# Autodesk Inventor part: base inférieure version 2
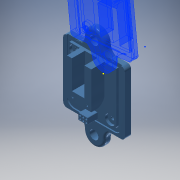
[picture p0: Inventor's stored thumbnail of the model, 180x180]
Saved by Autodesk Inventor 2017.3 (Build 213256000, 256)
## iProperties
Part Number: base inférieure version 2
Material: Plastique PMMA
Document SubType Name: Modeling
Designer: ficho
Density: 1.188 g/cm^3
Appearance: Pervenche
Mass: 23.0613 g
Surface Area: 101.506 cm^2
Volume: 19.4119 cm^3
Author: ficho
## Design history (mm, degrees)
node "Plan de construction1"
sketch "Esquisse1"
  geometry: L1 (4.5, -5.45)-(-4.5, -5.45) reference; L2 (4.5, 5.45)-(4.5, -5.45) reference; L3 (-4.5, 5.45)-(4.5, 5.45) reference; L4 (-4.5, -5.45)-(-4.5, 5.45) reference; L5 (-1.95, -7.7)-(4.55, -7.7) reference; L6 (-2.55, -9.12)-(-2.55, -8.3) reference; L7 (-2.096, -9.759)-(-2.308, -9.601) reference; L8 (-1.935, -10.8)-(-1.935, -10.08) reference; L9 (3.935, -11.4)-(-1.335, -11.4) reference; L10 (4.535, -10.08)-(4.535, -10.8) reference; L11 (4.908, -9.601)-(4.696, -9.759) reference; L12 (5.15, -8.3)-(5.15, -9.12) reference; L13 (-1.95, -8)-(4.55, -8) reference; L14 (4.85, -8.3)-(4.85, -9.12) reference; L15 (4.729, -9.361)-(4.517, -9.518) reference; L16 (4.235, -10.08)-(4.235, -10.8) reference; L17 (3.935, -11.1)-(-1.335, -11.1) reference; L18 (-1.635, -10.8)-(-1.635, -10.08) reference; L19 (-1.917, -9.518)-(-2.129, -9.361) reference; L20 (-2.25, -9.12)-(-2.25, -8.3) reference; L21 (-17.7, 15.45)-(20.2, 15.45); L22 (20.2, 15.45)-(20.2, -5.45); L23 (-17.7, -5.45)-(-17.7, 15.45); L24 (-5, -5.45)-(-17.7, -5.45); L25 (5, -5.45)-(20.2, -5.45); L26 (-5, -5.45)-(-5, 5.95); L27 (5, 5.95)-(5, -5.45); L28 (-5, 5.95)-(4.235, 5.95); L29 (4.5, 5.95)-(5, 5.95); L30 (-1.635, -5.95)-(-1.935, -5.95); L31 (-2.25, -5.95)-(-2.55, -5.95); L32 (5, -5.95)-(4.85, -5.95); L33 (4.535, -5.95)-(4.5, -5.95); L34 (4.5, 5.95)-(4.235, 5.95); C1 r 3.15 at (0, 0.95) reference; A1 r 0.6 centre (4.55, -8.3) between (5.15, -8.3) and (4.55, -7.7) reference; A2 r 0.6 centre (-1.95, -8.3) between (-1.95, -7.7) and (-2.55, -8.3) reference; A3 r 0.6 centre (-1.95, -9.12) between (-2.55, -9.12) and (-2.308, -9.601) reference; A4 r 0.4 centre (-2.335, -10.08) between (-1.935, -10.08) and (-2.096, -9.759) reference; A5 r 0.6 centre (-1.335, -10.8) between (-1.935, -10.8) and (-1.335, -11.4) reference; A6 r 0.6 centre (3.935, -10.8) between (3.935, -11.4) and (4.535, -10.8) reference; A7 r 0.4 centre (4.935, -10.08) between (4.696, -9.759) and (4.535, -10.08) reference; A8 r 0.6 centre (4.55, -9.12) between (4.908, -9.601) and (5.15, -9.12) reference; A9 r 0.3 centre (4.55, -8.3) between (4.85, -8.3) and (4.55, -8) reference; A10 r 0.3 centre (4.55, -9.12) between (4.729, -9.361) and (4.85, -9.12) reference; A11 r 0.7 centre (4.935, -10.08) between (4.517, -9.518) and (4.235, -10.08) reference; A12 r 0.3 centre (3.935, -10.8) between (3.935, -11.1) and (4.235, -10.8) reference; A13 r 0.3 centre (-1.335, -10.8) between (-1.635, -10.8) and (-1.335, -11.1) reference; A14 r 0.7 centre (-2.335, -10.08) between (-1.635, -10.08) and (-1.917, -9.518) reference; A15 r 0.3 centre (-1.95, -9.12) between (-2.25, -9.12) and (-2.129, -9.361) reference; A16 r 0.3 centre (-1.95, -8.3) between (-1.95, -8) and (-2.25, -8.3) reference; 3 further points
  constraints: 28 end point, 10 point on line, 2 perpendicular, 1 collinear, 1 horizontal, 1 parallel, 2 other
  dimensions: "d0" = 10 distance from line of point (-7.7, -6.45) L23; "d1" = 10 distance from line of L22 point (10.2, -6.45) (= d0); "d2" = 10 distance between parallel lines of L21 L3 (= d0); "d23" = 0.5 distance between parallel lines of L2 L27
extrude "Extrusion1" new body sketch "Esquisse1" stored distance "d4" = 1; taper "d5" = 0 deg
node "Plan de construction2"
sketch "Esquisse2"
  geometry: L1 (0, -20.9)-(15.2, -20.9) reference; L2 (25.34, -20.9)-(29.34, -20.9); L3 (29.34, -20.9)-(29.34, -4.794); L4 (29.34, -4.794)-(25.34, -4.794); L5 (25.34, -4.794)-(25.34, -20.9); L6 (9.7, -20.9)-(15.2, -20.9); L7 (15.2, -20.9)-(15.2, -4.794); L8 (15.2, -4.794)-(9.7, -4.794); L9 (9.7, -4.794)-(9.7, -20.9); 1 further point
  constraints: 16 end point, 4 parallel, 2 horizontal, 2 perpendicular
  dimensions: "d24" = 4 distance of L4.end L3.end
extrude "Extrusion2" join sketch "Esquisse2" stored distance "d10" = 10; taper "d11" = 0 deg
sketch "Esquisse3"
  geometry: L1 (1.85, 0)-(31.85, 0) reference; L2 (1.85, 16.106)-(31.85, 16.106) reference; L3 (31.85, 0)-(24.85, 0); L4 (24.85, 0)-(24.85, 16.106); L5 (24.85, 16.106)-(31.85, 16.106); L6 (31.85, 16.106)-(31.85, 0); 1 further point
  constraints: 8 end point, 2 parallel, 1 horizontal, 1 perpendicular, 1 point on line
  dimensions: "d12" = 7 distance of L4.end L5.end
extrude "Extrusion3" join sketch "Esquisse3" stored distance "d13" = 10; taper "d14" = 0 deg
sketch "Esquisse4"
  geometry: C1 r 1.5 at (2.7, -28.92) reference; C2 r 1.5 at (-9.2, -28.92) reference; 1 further point
hole "Perçage1" sketch "Esquisse4" at (2.7, -28.92), (-9.2, -28.92) diameter "d15" = 1.5; stored, may be unused: countersink angle "d19" = 90 deg, drill point angle "d21" = 118 deg; dims "d16" = 6, "d17" = 4, "d18" = 2, "d20" = 8
fillet "Congé1" dims "d22" = 7
sketch "Esquisse5"
  geometry: L1 (12.7, 0)-(0, 0) reference; L2 (0, 0)-(37.9, 0); L3 (37.9, 0)-(37.9, 50); L4 (37.9, 50)-(0, 50); L5 (0, 50)-(0, 0); 1 further point
  constraints: 8 end point, 2 parallel, 1 horizontal, 1 perpendicular
  dimensions: "d25" = 50 distance of L3.end L2.end
extrude "Extrusion4" join sketch "Esquisse5" distance "d26" = 5; taper "d27" = 0 deg
sketch "Esquisse6"
  geometry: L1 (0, 0)-(37.9, 0) reference; L2 (0, 50)-(0, 0) reference; L3 (37.9, 0)-(37.9, 50) reference; L4 (37.9, 50)-(0, 50) reference; 3 further points
  dimensions: "d28" = 6 distance from line of point (4, 6) L1; "d29" = 4 distance from line of point (4, 6) L2; "d31" = 5 distance from line of L3 point (32.9, 40); "d32" = 10 distance from line of point (32.9, 40) L4
hole "Perçage2" sketch "Esquisse6" at (4, 6), (32.9, 40) diameter "d33" = 2.5; stored, may be unused: countersink angle "d37" = 90 deg, drill point angle "d39" = 118 deg; dims "d34" = 6, "d35" = 4, "d36" = 2, "d38" = 8
sketch "Esquisse7"
  geometry: L1 (37.9, 0)-(37.9, 50) reference; L2 (0, 50)-(0, 0) reference; L3 (0, 0)-(37.9, 0) reference; L4 (2.45, 0)-(35.45, 0); C1 r 3.5 at (18.95, -8); A1 r 8 centre (2.45, -8) between (10.45, -8) and (2.45, 0); A2 r 8 centre (35.45, -8) between (35.45, 0) and (27.45, -8); A3 r 8.5 centre (18.95, -8) between (10.45, -8) and (27.45, -8); 1 further point
  constraints: 6 point on circle, 4 centre point, 2 end point, 2 point on line, 2 tangent
  dimensions: "d40" = 18.95 distance from line of C1.centre L1; "d41" = 18.95 distance from line of C1.centre L2 (derived); "d42" = 8 distance from line of L3 C1.centre; "d43" = 7 diameter of C1; "d45" = 8 distance from line of L3 A2.centre (= d42); "d46" = 8 distance from line of L3 A1.centre (= d42)
extrude "Extrusion5" join sketch "Esquisse7" distance "d47" = 4; taper "d48" = 0 deg
fillet "Congé2" dims "d49" = 2
node "Plan de construction3"
mirror "Symétrie1"
mirror "Symétrie2"
sketch "Esquisse8"
  geometry: C1 r 1.25 at (4, -6) reference; C2 r 1.9 at (32.9, -40) reference; C3 r 2 at (4, -6) reference; C4 r 4 at (4, -6); C5 r 4 at (32.9, -40); 1 further point
  constraints: 2 centre point, 2 coincident
  dimensions: "d51" = 8 diameter of C4; "d52" = 8 diameter of C5 (= d51)
extrude "Extrusion6" cut sketch "Esquisse8" distance "d53" = 2; taper "d54" = 0 deg
sketch "Esquisse9"
  geometry: 1 further point
sketch "Esquisse11"
  geometry: L1 (0, 0)-(-1.85, 0) reference; L2 (0, 20.9)-(-50, 20.9) reference; L3 (0, 0)-(-1.85, 0); L4 (-1.85, 0)-(-1.85, 20.9); L5 (-1.85, 20.9)-(0, 20.9); L6 (0, 20.9)-(0, 0); 1 further point
  constraints: 8 end point, 2 parallel, 1 horizontal, 1 perpendicular, 1 point on line
extrude "Extrusion8" join sketch "Esquisse11" distance "d57" = 3; taper "d58" = 0 deg
sketch "Esquisse12"
  geometry: L1 (0, 5)-(48.15, 5) reference; L2 (0, 5)-(48.15, 5); L3 (48.15, 5)-(48.15, 2); L4 (48.15, 2)-(2, 2); L5 (0, 2)-(0, 5); L6 (44, 0)-(0, 0) reference; L7 (0, 0)-(2, 0); L8 (2, 0)-(2, 2); L9 (0, 2)-(0, 0); L10 (48.15, 5)-(48.15, -15.9) reference; 1 further point
  constraints: 14 end point, 3 parallel, 2 horizontal, 2 perpendicular, 1 collinear, 1 point on line
  dimensions: "d59" = 3 distance between parallel lines of L1 L4
extrude "Extrusion9" join sketch "Esquisse12" distance "d61" = 3; taper "d62" = 0 deg
sketch "Esquisse13"
  geometry: L1 (0, 0)-(0, 20.9) reference; L2 (-50, 20.9)-(-50, 15.9) reference; L3 (0, 16.895)-(-50, 16.895); L4 (-50, 16.895)-(-50, 20.9); L5 (-50, 20.9)-(0, 20.9); L6 (0, 20.9)-(0, 16.895); 1 further point
  constraints: 8 end point, 2 parallel, 1 horizontal, 1 perpendicular, 1 point on line
extrude "Extrusion10" join sketch "Esquisse13" distance "d63" = 3; taper "d64" = 0 deg
sketch "Esquisse14"
  geometry: L1 (42, 2)-(0, 2) reference; L2 (0, 0)-(3, 0); L3 (3, 0)-(3, 2); L4 (3, 2)-(0, 2); L5 (0, 2)-(0, 0); 1 further point
  constraints: 8 end point, 2 parallel, 1 horizontal, 1 perpendicular, 1 point on line
  dimensions: "d65" = 3 distance of L4.end L3.end
extrude "Extrusion11" cut sketch "Esquisse14" stored distance "d66" = 3; taper "d67" = 0 deg
sketch "Esquisse15"
  geometry: L1 (0, 18.9)-(0, 20.9) reference; L2 (0, 16.895)-(0, 20.9); L3 (0, 20.9)-(50, 20.9); L4 (50, 20.9)-(50, 17.9); L5 (1.85, 0)-(0, 0) reference; L6 (0, 0)-(1.85, 0); L7 (1.85, 0)-(1.85, 16.895); L8 (0, 16.895)-(0, 0); L9 (48, 17.9)-(1.85, 17.9); L10 (1.85, 16.895)-(1.85, 17.9); L11 (50, 16.895)-(50, 17.9); L12 (50, 20.9)-(50, 15.9) reference; L13 (48, 16.895)-(48, 17.9); L14 (50, 16.895)-(48, 16.895); 1 further point
  constraints: 22 end point, 3 perpendicular, 2 parallel, 1 collinear, 1 horizontal, 1 vertical
extrude "Extrusion12" join sketch "Esquisse15" distance "d68" = 3; taper "d69" = 0 deg
sketch "Esquisse16"
  geometry: L1 (50, 20.9)-(0, 20.9) reference; L2 (50, 16.895)-(0, 16.895); L3 (0, 16.895)-(0, 20.9); L4 (0, 20.9)-(50, 20.9); L5 (50, 20.9)-(50, 16.895); L6 (48, 16.895)-(50, 16.895) reference; 1 further point
  constraints: 8 end point, 2 parallel, 1 collinear, 1 horizontal, 1 perpendicular
extrude "Extrusion13" join sketch "Esquisse16" distance "d70" = 3 (= d63); taper "d71" = 0 deg
sketch "Esquisse17"
  geometry: L1 (-48, 16.895)-(-50, 16.895) reference; L2 (-50, 16.895)-(-50, 15.9) reference; L3 (-50, 15.9)-(-48, 15.9) reference; L4 (-48, 15.9)-(-48, 16.895) reference; 1 further point
extrude "Extrusion14" cut sketch "Esquisse17" stored distance "d72" = 3; taper "d73" = 0 deg
fillet "Congé3" dims "d74" = 3 (= d63)
sketch "Esquisse18"
  geometry: L1 (-1.85, 15.9)-(-1.85, 17.9) reference; L2 (-1.85, 17.9)-(1.15, 17.9); L3 (1.15, 17.9)-(1.15, 0); L4 (1.15, 0)-(-1.85, 0); L5 (-1.85, 0)-(-1.85, 17.9); 1 further point
  constraints: 8 end point, 2 parallel, 1 horizontal, 1 perpendicular
  dimensions: "d75" = 3 distance of L3.end L4.end
extrude "Extrusion15" cut sketch "Esquisse18" stored distance "d76" = 3; taper "d77" = 0 deg
sketch "Esquisse19"
  geometry: L1 (-13.15, -6)-(30.05, -6) reference; L2 (-13.15, -6)-(-13.15, -7.6) reference; L3 (0, 9.106)-(0, 0) reference; L4 (0, 0)-(-7.15, 0); L5 (-13.15, 0)-(-13.15, 0); L6 (-10.15, 3)-(0, 3); L7 (0, 3)-(0, 0); L8 (-13.15, -6)-(-10.15, -6); L9 (-10.15, -6)-(-10.15, -3); L10 (-10.15, 0)-(-13.15, 0); L11 (-13.15, 0)-(-13.15, -6); A1 r 3 centre (-7.15, -3) between (-7.15, 0) and (-10.15, -3); A2 r 3 centre (-10.15, 0) between (-10.15, 3) and (-13.15, 0); 1 further point
  constraints: 16 end point, 4 parallel, 4 point on circle, 4 tangent, 3 point on line, 2 centre point, 2 horizontal, 2 perpendicular, 1 equal radius
  dimensions: "d78" = 3 distance between parallel lines of L11 L9; "d79" = 3 distance between parallel lines of L6 L4 (= d78); "d80" = 3 radius of A1
  node "Référence6"
  node "Référence7"
sketch "Esquisse20"
  geometry: L1 (24.95, 8)-(24.95, 9.85) reference; L2 (24.95, 8)-(24.95, 6.839); L3 (24.95, 6.839)-(12.349, 6.839); L4 (-24.885, 6.839)-(-12.407, 6.839); L5 (-12.407, 6.839)-(-12.349, 6.839); L6 (-24.95, 8)-(-24.95, 55) reference; L7 (-24.95, 8)-(-24.95, 6.839); L8 (-24.95, 6.839)-(-24.885, 6.839); L9 (16.5, 8)-(24.95, 8) reference; L10 (24.95, 8)-(16.5, 8); L11 (-24.95, 8)-(-16.5, 8) reference; L12 (-24.95, 8)-(-16.5, 8); A1 r 8 centre (16.5, 0) between (16.5, 8) and (8.5, 0) reference; A2 r 8 centre (-16.5, 0) between (-8.5, 0) and (-16.5, 8) reference; A3 r 8 centre (16.5, 0) between (16.5, 8) and (12.349, 6.839); A4 r 8 centre (-16.5, 0) between (-12.349, 6.839) and (-16.5, 8); 2 further points
  constraints: 16 end point, 6 point on circle, 4 point on line, 3 collinear, 2 centre point, 2 concentric, 2 perpendicular, 1 vertical, 1 other
extrude "Extrusion16" join sketch "Esquisse20" stored distance "d81" = 10; taper "d82" = 0 deg
node "Plan de construction4"
sketch "Esquisse22"
  geometry: L1 (0, -45)-(37.9, -45) reference; L2 (3, -45)-(0, -45); L3 (0, -45)-(0, -42); L4 (37.9, -42)-(37.9, -45); L5 (37.9, -45)-(34.9, -45); A1 r 3 centre (3, -42) between (0, -42) and (3, -45) reference; A2 r 3 centre (34.9, -42) between (34.9, -45) and (37.9, -42) reference; 1 further point
  constraints: 8 end point, 3 tangent, 2 perpendicular, 1 collinear, 1 parallel, 1 point on line
extrude "Extrusion17" cut sketch "Esquisse22" stored distance "d84" = 10; taper "d85" = 0 deg
fillet "Congé4" dims "d86" = 3
node "Plan de construction5"
node "Plan de construction6"
sketch "Esquisse24"
  geometry: L1 (22.81, -40.323)-(22.81, -44.323) reference; L2 (15.19, -44.323)-(15.19, -40.323) reference; L3 (22.31, -39.823)-(15.69, -39.823); L4 (22.31, -44.823)-(15.69, -44.823); C1 r 0.9 at (19, -43.593) reference; C2 r 0.9 at (16.46, -43.593) reference; C3 r 0.9 at (16.46, -41.053) reference; C4 r 0.9 at (19, -41.053) reference; C5 r 0.9 at (21.54, -41.053) reference; C6 r 0.9 at (21.54, -43.593) reference; A1 r 0.5 centre (15.69, -44.323) between (15.19, -44.323) and (15.69, -44.823) reference; A2 r 0.5 centre (22.31, -44.323) between (22.31, -44.823) and (22.81, -44.323) reference; A3 r 0.5 centre (22.31, -40.323) between (22.81, -40.323) and (22.31, -39.823) reference; A4 r 0.5 centre (15.69, -40.323) between (15.69, -39.823) and (15.19, -40.323) reference; 1 further point
  constraints: 10 centre point, 8 end point, 8 point on circle, 2 vertical, 1 horizontal, 1 parallel, 1 tangent, 28 other
node "Plan de construction7"
extrude "Extrusion19" join sketch "Esquisse24" distance "d89" = 8; taper "d90" = 0 deg
fillet "Congé5" dims "d91" = 5.5
fillet "Congé6" dims "d92" = 5.5
sketch "Esquisse25"
  geometry: L1 (36.82, -3)-(33.82, -3) reference; L2 (33.809, -3.011)-(33.82, 0); L3 (36.82, -3.011)-(33.809, -3.011); L4 (-10.08, -3)-(-13.08, -3) reference; L5 (-10.08, -3)-(-10.08, 0.011); L6 (-10.08, -3)-(-13.08, -3) reference; L7 (-10.08, -3)-(-13.08, -3); L8 (-10.08, -3)-(-13.08, -3); A1 r 3.011 centre (33.809, -3.011) between (36.82, -3.011) and (33.82, 0) reference; A2 r 3 centre (-10.08, -3) between (-10.08, 0) and (-13.08, -3); 1 further point
  constraints: 10 end point, 4 point on circle, 2 centre point, 2 horizontal, 1 coincident, 1 collinear, 1 point on line, 1 vertical, 4 other
extrude "Extrusion20" join sketch "Esquisse25" stored distance "d93" = 10; taper "d94" = 0 deg
sketch "Esquisse26"
  geometry: L1 (-13.2, 5.4)-(30, 5.4) reference; L2 (36.736, 5.4)-(-1.96, 5.4); L3 (-1.96, 5.4)-(-1.96, -2.041); L4 (-1.96, -2.041)-(36.736, -2.041); L5 (36.736, -2.041)-(36.736, 5.4); 1 further point
  constraints: 8 end point, 2 parallel, 1 horizontal, 1 perpendicular
extrude "Extrusion21" cut sketch "Esquisse26" stored distance "d95" = 10; taper "d96" = 0 deg
sketch "Esquisse27"
  geometry: L1 (-21.95, 6.839)-(-12.349, 6.839) reference; L2 (21.95, 6.839)-(12.349, 6.839) reference; L3 (24.95, 55)-(24.95, 9.839) reference; L4 (21.95, 58)-(16.5, 58) reference; L5 (-16.5, 58)-(-21.95, 58) reference; L6 (-24.95, 55)-(-24.95, 9.839) reference; C1 r 3.5 at (0, 66) reference; C2 r 3.5 at (0, 0) reference; C3 r 2 at (-14.95, 14) reference; C4 r 2 at (13.95, 48) reference; A1 r 3 centre (-21.95, 9.839) between (-24.95, 9.839) and (-21.95, 6.839) reference; A2 r 8 centre (-16.5, 0) between (-8.5, 0) and (-12.349, 6.839) reference; A3 r 8.5 centre (0, 0) between (-8.5, 0) and (8.5, 0) reference; A4 r 8 centre (16.5, 0) between (12.349, 6.839) and (8.5, 0) reference; A5 r 3 centre (21.95, 9.839) between (21.95, 6.839) and (24.95, 9.839) reference; A6 r 3 centre (21.95, 55) between (24.95, 55) and (21.95, 58) reference; A7 r 8 centre (16.5, 66) between (8.5, 66) and (16.5, 58) reference; A8 r 8.5 centre (0, 66) between (8.5, 66) and (-8.5, 66) reference; A9 r 8 centre (-16.5, 66) between (-16.5, 58) and (-8.5, 66) reference; A10 r 3 centre (-21.95, 55) between (-21.95, 58) and (-24.95, 55) reference; 1 further point
  node "Boucle projetée2"
node "Plan de construction8"
extrude "Extrusion22" join sketch "Esquisse27" stored distance "d97" = 10; taper "d98" = 0 deg
node "Solide1"
node "Référence1"
node "Référence2"
node "Référence3"
node "Référence4"
node "Référence5"
node "Boucle projetée1"
node "Référence8"
node "Référence9"
node "Référence10"
other parameters: "d44" = 5, "d50" = -25
